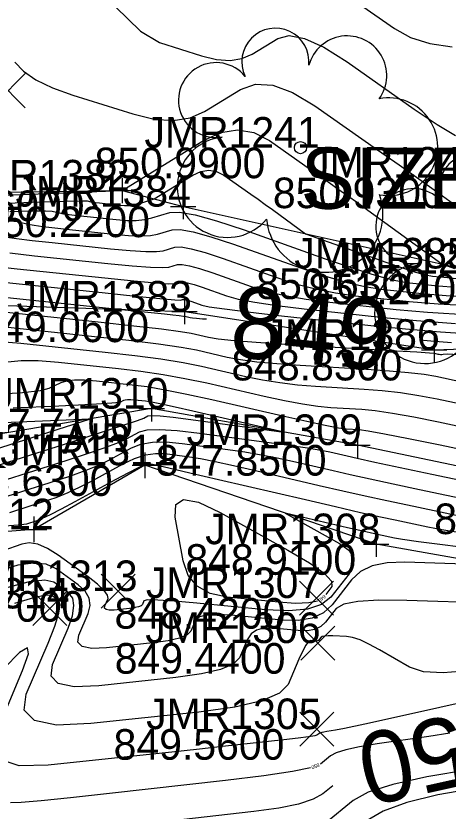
# Model space of a CAD drawing. Extents: x 1654928 to 1810050, y 486881 to 626330.
# Drawn here: x 1801514.13 to 1801531.06, y 489829.65 to 489860.85 of the extents above; entities that cross this region are included whole.
import ezdxf

# ---------------------------------------------------------------- set-up
doc = ezdxf.new("R2010")
doc.units = 0
for name, color, linetype in [('DR_X_Ditch', 7, 'Continuous'), ('DT_X_Contour_Major', 7, 'Continuous'), ('DT_X_Contour_Minor', 7, 'Continuous'), ('SV_X_Random_Point', 7, 'Continuous'), ('SV_X_Shot_Marker', 7, 'Continuous'), ('SV_X_Text_Comment', 7, 'Continuous'), ('SV_X_Text_Elevation', 7, 'Continuous'), ('SV_X_Text_Name', 7, 'Continuous'), ('SV_X_Toe_of_Slope', 7, 'Continuous'), ('SV_X_Top_of_Bank', 7, 'Continuous'), ('VG_X_Cells', 7, 'Continuous'), ('VG_X_Text', 7, 'Continuous')]:
    doc.layers.add(name, color=color, linetype=linetype)

msp = doc.modelspace()

# ---------------------------------------------------------------- linework, layer by layer
at = {"layer": 'DR_X_Ditch'}
msp.add_lwpolyline([(1801538.429, 489841.719), (1801527.515, 489844.014), (1801519.444, 489845.441), (1801503.521, 489842.761), (1801490.506, 489842.113), (1801478.561, 489839.498), (1801468.658, 489833.373), (1801465.597, 489830.762), (1801453.487, 489824.594)], dxfattribs=at)
at = {"layer": 'DT_X_Contour_Major'}
for points in [[(1801518.035, 489861.209), (1801519.01, 489860.254), (1801519.748, 489859.805), (1801521.403, 489859.283), (1801521.993, 489859.14), (1801522.52, 489859.104), (1801522.987, 489859.174), (1801523.391, 489859.351), (1801524.387, 489859.963), (1801524.837, 489860.077), (1801525.44, 489859.962), (1801526.197, 489859.615), (1801527.106, 489859.039), (1801529.736, 489857.194), (1801530.633, 489856.59), (1801531.351, 489856.161)], [(1801513.898, 489852.81), (1801514.172, 489852.781), (1801514.612, 489852.677), (1801514.837, 489852.634), (1801515.182, 489852.585), (1801515.647, 489852.528), (1801516.231, 489852.464), (1801517.95, 489852.283), (1801518.541, 489852.232), (1801519.025, 489852.215), (1801519.403, 489852.23), (1801519.674, 489852.28), (1801520.255, 489852.455), (1801520.568, 489852.469), (1801521.073, 489852.38), (1801521.77, 489852.186), (1801522.658, 489851.889), (1801525.281, 489850.958), (1801526.216, 489850.645), (1801527.055, 489850.402), (1801527.797, 489850.23), (1801528.443, 489850.129), (1801530.036, 489849.953), (1801530.982, 489849.881), (1801532.625, 489849.795)], [(1801512.039, 489849.987), (1801518.264, 489849.333), (1801519.952, 489849.156), (1801520.276, 489849.121), (1801520.524, 489849.092), (1801520.696, 489849.069), (1801520.793, 489849.052), (1801520.951, 489849.016), (1801521.044, 489849.002), (1801521.205, 489848.986), (1801521.435, 489848.969), (1801521.597, 489848.958)], [(1801529.956, 489848.137), (1801530.391, 489848.098), (1801531.202, 489848.038)], [(1801534.445, 489843.224), (1801530.748, 489844.002), (1801529.51, 489844.259), (1801528.571, 489844.445), (1801527.929, 489844.562), (1801527.585, 489844.609), (1801527.064, 489844.64), (1801526.763, 489844.68), (1801526.25, 489844.777), (1801525.525, 489844.931), (1801524.588, 489845.142), (1801521.807, 489845.78), (1801520.829, 489845.996), (1801519.981, 489846.166), (1801519.265, 489846.29), (1801518.678, 489846.368), (1801517.289, 489846.514), (1801516.811, 489846.552), (1801516.418, 489846.554), (1801516.112, 489846.521), (1801515.892, 489846.454), (1801515.42, 489846.226), (1801515.072, 489846.143), (1801514.382, 489846.065), (1801513.351, 489845.992)], [(1801512.593, 489842.29), (1801515.728, 489843.29), (1801516.781, 489843.631), (1801517.588, 489843.905), (1801518.149, 489844.111), (1801518.464, 489844.25), (1801518.977, 489844.53), (1801519.268, 489844.605), (1801519.757, 489844.621), (1801520.443, 489844.578), (1801521.327, 489844.476), (1801523.948, 489844.124), (1801524.84, 489844.002), (1801525.55, 489843.897), (1801526.078, 489843.81), (1801526.425, 489843.741), (1801527.107, 489843.583), (1801527.506, 489843.494), (1801528.193, 489843.345), (1801530.429, 489842.872), (1801534.177, 489842.084)], [(1801532.898, 489839.299), (1801529.368, 489839.415), (1801528.67, 489839.391), (1801528.09, 489839.268), (1801527.627, 489839.047), (1801527.281, 489838.728), (1801526.515, 489837.744), (1801526.177, 489837.43), (1801525.737, 489837.225), (1801525.194, 489837.129), (1801524.55, 489837.142), (1801522.696, 489837.322), (1801522.08, 489837.361), (1801521.619, 489837.344), (1801521.316, 489837.27), (1801521.169, 489837.139), (1801520.985, 489836.714), (1801520.84, 489836.565), (1801520.542, 489836.438), (1801520.092, 489836.333), (1801519.488, 489836.249), (1801517.676, 489836.055), (1801517.098, 489836.032), (1801516.724, 489836.107), (1801516.555, 489836.281), (1801516.59, 489836.553), (1801516.954, 489837.411), (1801517.033, 489837.722), (1801516.995, 489838.012), (1801516.842, 489838.281), (1801516.573, 489838.529), (1801515.701, 489839.162), (1801515.317, 489839.336), (1801514.819, 489839.38), (1801514.207, 489839.296), (1801513.482, 489839.083)], [(1801526.541, 489830.649), (1801526.157, 489830.333), (1801525.78, 489830.118), (1801525.204, 489829.93), (1801524.429, 489829.769), (1801523.455, 489829.635), (1801520.593, 489829.314), (1801519.572, 489829.211), (1801518.658, 489829.145), (1801517.85, 489829.115), (1801517.148, 489829.12), (1801515.416, 489829.184), (1801514.789, 489829.203), (1801514.203, 489829.213), (1801513.661, 489829.214)]]:
    msp.add_lwpolyline(points, dxfattribs=at)
at = {"layer": 'DT_X_Contour_Minor'}
for points in [[(1801527.426, 489861.424), (1801528.96, 489860.348), (1801529.595, 489859.999), (1801530.348, 489859.76), (1801531.219, 489859.631)], [(1801514.082, 489859.034), (1801514.42, 489858.676), (1801514.913, 489858.34), (1801515.56, 489858.028), (1801516.362, 489857.739), (1801518.706, 489857), (1801519.542, 489856.798), (1801520.29, 489856.746), (1801520.95, 489856.846), (1801521.523, 489857.096), (1801522.934, 489857.963), (1801523.512, 489858.167), (1801524.189, 489858.127), (1801524.964, 489857.844), (1801525.838, 489857.318), (1801528.3, 489855.592), (1801529.142, 489855), (1801529.822, 489854.52), (1801530.341, 489854.152), (1801530.697, 489853.896), (1801531.712, 489853.159)], [(1801510.049, 489853.677), (1801518.285, 489853.998), (1801521.481, 489855.963), (1801522.155, 489856.278), (1801522.81, 489856.382), (1801523.445, 489856.275), (1801524.06, 489855.956), (1801525.672, 489854.825), (1801526.275, 489854.4), (1801526.874, 489853.974), (1801527.47, 489853.547), (1801528.062, 489853.119), (1801530.815, 489851.116), (1801531.31, 489850.941)], [(1801513.758, 489853.5), (1801515.098, 489853.55), (1801516.07, 489853.582), (1801516.676, 489853.596), (1801516.914, 489853.593), (1801517.061, 489853.558), (1801517.136, 489853.544), (1801517.251, 489853.527), (1801517.406, 489853.508), (1801518.174, 489853.427), (1801518.379, 489853.412), (1801518.566, 489853.414), (1801518.735, 489853.433), (1801518.886, 489853.467), (1801519.546, 489853.667), (1801521.06, 489854.597), (1801521.379, 489854.747), (1801521.689, 489854.796), (1801521.99, 489854.745), (1801522.281, 489854.594), (1801523.331, 489853.857), (1801523.615, 489853.655), (1801523.897, 489853.453), (1801524.177, 489853.25), (1801525.481, 489852.302), (1801528.659, 489851.174), (1801529.282, 489850.96), (1801529.789, 489850.8), (1801530.181, 489850.694), (1801530.457, 489850.643), (1801531.039, 489850.579), (1801531.384, 489850.552)], [(1801513.895, 489853.179), (1801514.737, 489853.201), (1801515.287, 489853.203), (1801515.543, 489853.187), (1801515.837, 489853.117), (1801515.987, 489853.089), (1801516.217, 489853.056), (1801516.526, 489853.018), (1801516.916, 489852.975), (1801518.062, 489852.855), (1801518.471, 489852.825), (1801518.838, 489852.827), (1801519.164, 489852.86), (1801519.449, 489852.924), (1801520.153, 489853.138), (1801520.534, 489853.154), (1801521.146, 489853.046), (1801521.991, 489852.811), (1801523.067, 489852.451), (1801526.248, 489851.322), (1801527.343, 489850.946), (1801528.242, 489850.665), (1801528.944, 489850.478), (1801529.45, 489850.386), (1801530.537, 489850.266), (1801531.183, 489850.216)], [(1801513.688, 489852.18), (1801514.148, 489852.114), (1801514.767, 489852.038), (1801515.547, 489851.952), (1801517.838, 489851.712), (1801518.611, 489851.639), (1801519.213, 489851.602), (1801519.642, 489851.601), (1801519.899, 489851.635), (1801520.356, 489851.773), (1801520.603, 489851.784), (1801521.001, 489851.713), (1801521.549, 489851.561), (1801522.248, 489851.327), (1801524.313, 489850.595), (1801525.089, 489850.343), (1801525.868, 489850.139), (1801526.65, 489849.982), (1801527.436, 489849.872), (1801529.535, 489849.64), (1801530.679, 489849.548), (1801532.536, 489849.446)], [(1801513.888, 489851.548), (1801514.862, 489851.441), (1801517.726, 489851.14), (1801518.682, 489851.046), (1801519.4, 489850.99), (1801519.881, 489850.971), (1801520.124, 489850.99), (1801520.458, 489851.091), (1801520.638, 489851.099), (1801520.928, 489851.047), (1801521.328, 489850.936), (1801521.838, 489850.765), (1801523.345, 489850.231), (1801523.962, 489850.042), (1801524.681, 489849.876), (1801525.504, 489849.734), (1801526.429, 489849.615), (1801529.034, 489849.328), (1801530.25, 489849.221), (1801531.944, 489849.115)], [(1801513.008, 489851.057), (1801514.177, 489850.929), (1801517.614, 489850.568), (1801518.752, 489850.453), (1801519.587, 489850.377), (1801520.12, 489850.341), (1801520.35, 489850.345), (1801520.56, 489850.409), (1801520.673, 489850.414), (1801520.856, 489850.381), (1801521.108, 489850.311), (1801521.429, 489850.204), (1801522.377, 489849.867), (1801522.835, 489849.741), (1801523.494, 489849.613), (1801524.357, 489849.486), (1801525.422, 489849.358), (1801528.533, 489849.015), (1801529.821, 489848.893), (1801531.352, 489848.784)], [(1801513.493, 489850.418), (1801517.503, 489849.996), (1801518.822, 489849.859), (1801519.774, 489849.764), (1801520.358, 489849.711), (1801520.575, 489849.7), (1801520.661, 489849.726), (1801520.708, 489849.728), (1801520.783, 489849.715), (1801520.887, 489849.686), (1801521.019, 489849.642), (1801521.41, 489849.503), (1801521.707, 489849.439), (1801522.308, 489849.351), (1801523.21, 489849.238), (1801524.415, 489849.1), (1801528.032, 489848.702), (1801529.392, 489848.565), (1801530.76, 489848.453), (1801532.136, 489848.367)], [(1801508.55, 489849.771), (1801517.349, 489848.845), (1801518.753, 489848.693), (1801519.828, 489848.568), (1801520.576, 489848.47), (1801520.996, 489848.398), (1801521.678, 489848.241), (1801522.056, 489848.181), (1801522.68, 489848.116), (1801523.548, 489848.048), (1801524.661, 489847.976), (1801529.043, 489847.714), (1801529.834, 489847.664), (1801530.329, 489847.63), (1801530.527, 489847.611), (1801530.661, 489847.583), (1801530.712, 489847.575), (1801530.765, 489847.571), (1801530.82, 489847.571), (1801530.876, 489847.576), (1801531.029, 489847.594), (1801531.476, 489847.568)], [(1801512.83, 489848.736), (1801517.095, 489848.287), (1801518.551, 489848.127), (1801519.72, 489847.983), (1801520.602, 489847.855), (1801521.198, 489847.743), (1801522.406, 489847.466), (1801522.924, 489847.368), (1801523.572, 489847.281), (1801524.352, 489847.206), (1801525.262, 489847.142), (1801527.863, 489846.987), (1801528.765, 489846.926), (1801529.518, 489846.859), (1801530.124, 489846.787), (1801530.582, 489846.709), (1801531.607, 489846.494)], [(1801532.553, 489845.404), (1801530.638, 489845.807), (1801529.92, 489845.944), (1801529.202, 489846.055), (1801528.486, 489846.138), (1801527.77, 489846.194), (1801525.863, 489846.308), (1801525.156, 489846.364), (1801524.465, 489846.447), (1801523.791, 489846.556), (1801523.133, 489846.691), (1801521.401, 489847.089), (1801520.678, 489847.236), (1801519.807, 489847.378), (1801518.789, 489847.515), (1801517.623, 489847.648), (1801514.316, 489847.995), (1801513.179, 489848.084)], [(1801533.499, 489844.314), (1801530.693, 489844.904), (1801529.715, 489845.101), (1801528.887, 489845.25), (1801528.207, 489845.35), (1801527.677, 489845.401), (1801526.464, 489845.474), (1801525.959, 489845.522), (1801525.358, 489845.612), (1801524.658, 489845.743), (1801523.861, 489845.917), (1801521.604, 489846.434), (1801520.753, 489846.616), (1801519.894, 489846.772), (1801519.027, 489846.903), (1801518.15, 489847.008), (1801515.802, 489847.255), (1801514.995, 489847.318), (1801514.332, 489847.322), (1801513.815, 489847.266)], [(1801511.944, 489842.749), (1801515.988, 489844.039), (1801517.322, 489844.466), (1801518.292, 489844.78), (1801518.898, 489844.982), (1801519.14, 489845.071), (1801519.299, 489845.158), (1801519.449, 489845.173), (1801519.779, 489845.154), (1801520.291, 489845.101), (1801520.982, 489845.013), (1801524.632, 489844.523), (1801521.06, 489845.343), (1801520.37, 489845.499), (1801519.831, 489845.615), (1801519.443, 489845.692), (1801519.206, 489845.729), (1801518.775, 489845.774), (1801518.626, 489845.785), (1801518.505, 489845.786), (1801518.41, 489845.776), (1801518.341, 489845.755), (1801518.195, 489845.684), (1801517.893, 489845.65), (1801517.095, 489845.601), (1801515.804, 489845.536), (1801514.017, 489845.457)], [(1801510.41, 489842.926), (1801517.011, 489845.031), (1801508.098, 489844.648)], [(1801513.243, 489841.831), (1801515.469, 489842.541), (1801516.24, 489842.796), (1801516.884, 489843.029), (1801517.4, 489843.24), (1801517.789, 489843.428), (1801518.656, 489843.901), (1801519.024, 489844.045), (1801519.478, 489844.123), (1801520.02, 489844.133), (1801520.647, 489844.076), (1801522.436, 489843.836), (1801523.097, 489843.74), (1801523.74, 489843.632), (1801524.365, 489843.511), (1801524.971, 489843.378), (1801526.562, 489843.008), (1801527.221, 489842.857), (1801528.005, 489842.684), (1801528.914, 489842.487), (1801529.948, 489842.268), (1801532.873, 489841.653)], [(1801513.892, 489841.372), (1801515.21, 489841.792), (1801515.699, 489841.961), (1801516.18, 489842.153), (1801516.651, 489842.368), (1801517.113, 489842.607), (1801518.334, 489843.273), (1801518.779, 489843.486), (1801519.2, 489843.624), (1801519.596, 489843.687), (1801519.967, 489843.676), (1801520.924, 489843.548), (1801521.355, 489843.479), (1801521.931, 489843.367), (1801522.651, 489843.212), (1801523.517, 489843.015), (1801526.017, 489842.432), (1801526.936, 489842.221), (1801527.817, 489842.022), (1801528.661, 489841.837), (1801529.468, 489841.664), (1801531.568, 489841.223)], [(1801531.53, 489840.572), (1801530.82, 489840.687), (1801530.264, 489840.792), (1801528.987, 489841.06), (1801528.408, 489841.186), (1801527.63, 489841.36), (1801526.651, 489841.584), (1801525.472, 489841.857), (1801522.062, 489842.652), (1801520.938, 489842.913), (1801520.121, 489843.102), (1801519.612, 489843.217), (1801519.412, 489843.26), (1801519.287, 489843.277), (1801519.172, 489843.242), (1801518.921, 489843.125), (1801518.535, 489842.926), (1801518.012, 489842.645), (1801516.438, 489841.785), (1801515.902, 489841.497), (1801515.476, 489841.278), (1801515.158, 489841.126), (1801514.95, 489841.043), (1801514.541, 489840.913), (1801514.21, 489840.864), (1801513.521, 489840.815)], [(1801520.374, 489841.187), (1801520.398, 489841.681), (1801520.699, 489841.875), (1801521.277, 489841.771), (1801522.132, 489841.367), (1801524.78, 489839.893), (1801525.633, 489839.389), (1801526.206, 489838.982), (1801526.499, 489838.673), (1801526.512, 489838.461), (1801526.266, 489838.145)], [(1801532.074, 489839.943), (1801530.839, 489840.099), (1801529.908, 489840.221), (1801529.282, 489840.308), (1801528.96, 489840.361), (1801528.293, 489840.503), (1801527.6, 489840.66), (1801527.122, 489840.771), (1801524.684, 489841.339), (1801526.808, 489840.156), (1801527.173, 489839.892), (1801527.357, 489839.604), (1801527.36, 489839.294), (1801527.182, 489838.961), (1801526.466, 489838.042), (1801526.105, 489837.753), (1801525.558, 489837.574), (1801524.826, 489837.507), (1801523.907, 489837.55), (1801521.211, 489837.812), (1801520.323, 489837.891), (1801519.683, 489837.933), (1801519.289, 489837.936), (1801519.143, 489837.902), (1801519.082, 489837.76), (1801519.033, 489837.711), (1801518.934, 489837.669), (1801518.784, 489837.634), (1801518.583, 489837.606), (1801517.979, 489837.541), (1801517.786, 489837.533), (1801517.662, 489837.558), (1801517.605, 489837.616), (1801517.617, 489837.707), (1801517.738, 489837.993), (1801517.723, 489838.127), (1801517.587, 489838.313), (1801517.331, 489838.552), (1801516.953, 489838.843), (1801515.785, 489839.691), (1801515.367, 489839.957), (1801514.989, 489840.119), (1801514.652, 489840.176), (1801514.354, 489840.13), (1801513.614, 489839.868)], [(1801525.945, 489837.887), (1801525.607, 489837.818), (1801525.089, 489837.802), (1801524.416, 489837.846), (1801522.412, 489838.04), (1801521.74, 489838.185), (1801521.227, 489838.471), (1801520.874, 489838.901), (1801520.679, 489839.472), (1801520.374, 489841.187)], [(1801532.7, 489837.813), (1801529.44, 489837.921), (1801528.351, 489837.931), (1801527.529, 489837.881), (1801526.972, 489837.77), (1801526.682, 489837.599), (1801526.265, 489837.063), (1801526.08, 489836.891), (1801525.84, 489836.779), (1801525.544, 489836.727), (1801525.193, 489836.734), (1801524.182, 489836.832), (1801523.836, 489836.831), (1801523.556, 489836.755), (1801523.342, 489836.603), (1801523.194, 489836.375), (1801522.889, 489835.667), (1801522.647, 489835.419), (1801522.15, 489835.208), (1801521.399, 489835.033), (1801520.394, 489834.893), (1801517.373, 489834.57), (1801516.41, 489834.531), (1801515.787, 489834.656), (1801515.505, 489834.946), (1801515.563, 489835.4), (1801516.17, 489836.829), (1801516.342, 489837.318), (1801516.403, 489837.712), (1801516.353, 489838.011), (1801516.193, 489838.215), (1801515.616, 489838.634), (1801515.266, 489838.714), (1801514.648, 489838.641), (1801513.763, 489838.415)], [(1801531.855, 489835.16), (1801530.865, 489835.071), (1801530.095, 489835.12), (1801529.545, 489835.305), (1801528.373, 489835.984), (1801527.963, 489836.207), (1801527.612, 489836.369), (1801527.32, 489836.468), (1801527.087, 489836.506), (1801526.543, 489836.524), (1801526.362, 489836.526), (1801526.225, 489836.517), (1801526.132, 489836.499), (1801526.084, 489836.47), (1801526.014, 489836.381), (1801525.983, 489836.352), (1801525.943, 489836.334), (1801525.894, 489836.325), (1801525.836, 489836.326), (1801525.667, 489836.343), (1801525.592, 489836.302), (1801525.492, 489836.166), (1801525.368, 489835.936), (1801525.22, 489835.611), (1801524.792, 489834.62), (1801524.453, 489834.274), (1801523.758, 489833.977), (1801522.707, 489833.732), (1801521.299, 489833.537), (1801517.07, 489833.084), (1801515.722, 489833.029), (1801514.85, 489833.205), (1801514.455, 489833.61), (1801514.536, 489834.246), (1801515.386, 489836.247), (1801515.651, 489836.914), (1801515.811, 489837.412), (1801515.865, 489837.741), (1801515.813, 489837.902), (1801515.532, 489838.105), (1801515.3, 489838.123), (1801514.814, 489838.022), (1801514.075, 489837.803)], [(1801513.418, 489832.88), (1801514.391, 489835.17), (1801514.62, 489835.821), (1801514.579, 489836.055), (1801514.266, 489835.872), (1801513.682, 489835.272)], [(1801535.845, 489834.855), (1801530.737, 489833.714), (1801529.045, 489833.338), (1801527.8, 489833.063), (1801527.002, 489832.891), (1801526.652, 489832.822), (1801526.313, 489832.772), (1801526.199, 489832.754), (1801526.11, 489832.734), (1801526.047, 489832.714), (1801526.009, 489832.694), (1801525.942, 489832.639), (1801525.841, 489832.611), (1801525.588, 489832.572), (1801525.184, 489832.52), (1801524.628, 489832.455), (1801522.223, 489832.186), (1801521.323, 489832.088), (1801520.243, 489831.971), (1801518.984, 489831.836), (1801515.387, 489831.451), (1801514.252, 489831.432), (1801513.546, 489831.663)], [(1801531.129, 489832.716), (1801530.308, 489832.584), (1801528.278, 489832.289), (1801527.593, 489832.176), (1801527.06, 489832.06), (1801526.68, 489831.941), (1801526.453, 489831.818), (1801526.058, 489831.492)], [(1801548.136, 489829.56), (1801547.136, 489829.805), (1801546.149, 489830.07), (1801545.175, 489830.354), (1801542.596, 489831.137), (1801541.737, 489831.393), (1801541.094, 489831.574), (1801540.667, 489831.681), (1801540.456, 489831.712), (1801540.182, 489831.696), (1801539.883, 489831.66), (1801539.192, 489831.565), (1801538.11, 489831.41), (1801536.636, 489831.197), (1801532.182, 489830.548), (1801530.662, 489830.287), (1801529.441, 489829.989), (1801528.52, 489829.655), (1801527.898, 489829.284)], [(1801525.666, 489831.345), (1801524.97, 489831.203), (1801523.848, 489831.037), (1801522.337, 489830.854), (1801517.79, 489830.344), (1801516.27, 489830.177), (1801515.118, 489830.061), (1801514.335, 489829.994), (1801513.92, 489829.978)], [(1801531.947, 489831.284), (1801530.234, 489831), (1801528.895, 489830.702), (1801527.93, 489830.391), (1801527.34, 489830.066), (1801526.264, 489829.18)]]:
    msp.add_lwpolyline(points, dxfattribs=at)
at = {"layer": 'SV_X_Random_Point'}
for p, q in [((1801513.157, 489857.246), (1801514.49, 489858.581)), ((1801513.157, 489858.581), (1801514.49, 489857.246)), ((1801517.463, 489837.616), (1801518.797, 489838.951)), ((1801517.463, 489838.951), (1801518.797, 489837.616)), ((1801525.243, 489837.344), (1801526.576, 489838.679)), ((1801525.243, 489838.679), (1801526.576, 489837.344)), ((1801514.785, 489836.936), (1801516.118, 489838.271)), ((1801514.785, 489838.271), (1801516.118, 489836.936)), ((1801525.297, 489835.577), (1801526.631, 489836.912)), ((1801525.297, 489836.912), (1801526.631, 489835.577)), ((1801525.254, 489832.202), (1801526.587, 489833.537)), ((1801525.254, 489833.537), (1801526.587, 489832.202))]:
    msp.add_line(p, q, dxfattribs=at)
at = {"layer": 'SV_X_Shot_Marker'}
for p, q in [((1801518.285, 489854.498), (1801518.285, 489853.498)), ((1801517.785, 489853.998), (1801518.785, 489853.998)), ((1801518.285, 489853.998), (1801518.285, 489853.998)), ((1801520.681, 489853.868), (1801520.681, 489852.868)), ((1801520.181, 489853.368), (1801521.181, 489853.368)), ((1801520.681, 489853.368), (1801520.681, 489853.368)), ((1801520.732, 489849.749), (1801520.732, 489848.749)), ((1801520.232, 489849.249), (1801521.232, 489849.249)), ((1801520.732, 489849.249), (1801520.732, 489849.249)), ((1801530.519, 489848.247), (1801530.519, 489847.247)), ((1801530.019, 489847.747), (1801531.019, 489847.747)), ((1801530.519, 489847.747), (1801530.519, 489847.747)), ((1801519.444, 489845.941), (1801519.444, 489844.941)), ((1801518.944, 489845.441), (1801519.944, 489845.441)), ((1801519.444, 489845.441), (1801519.444, 489845.441)), ((1801527.515, 489844.514), (1801527.515, 489843.514)), ((1801527.015, 489844.014), (1801528.015, 489844.014)), ((1801527.515, 489844.014), (1801527.515, 489844.014)), ((1801519.185, 489843.717), (1801519.185, 489842.717)), ((1801518.685, 489843.217), (1801519.685, 489843.217)), ((1801519.185, 489843.217), (1801519.185, 489843.217)), ((1801514.834, 489841.206), (1801514.834, 489840.206)), ((1801514.334, 489840.706), (1801515.334, 489840.706)), ((1801514.834, 489840.706), (1801514.834, 489840.706)), ((1801528.242, 489840.624), (1801528.242, 489839.624)), ((1801527.742, 489840.124), (1801528.742, 489840.124)), ((1801528.242, 489840.124), (1801528.242, 489840.124))]:
    msp.add_line(p, q, dxfattribs=at)
at = {"layer": 'SV_X_Toe_of_Slope'}
for points in [[(1801453.22, 489833.952), (1801462.62, 489833.764), (1801469.81, 489840.55), (1801480.323, 489844.16), (1801485.248, 489845.996), (1801491.16, 489848.502), (1801498.28, 489846.461), (1801505.556, 489847.392), (1801507.978, 489849.684), (1801520.732, 489849.249), (1801530.519, 489847.747), (1801557.678, 489848.692)], [(1801548.771, 489840.76), (1801538.587, 489838.29), (1801528.242, 489840.124), (1801519.185, 489843.217), (1801514.834, 489840.706), (1801503.746, 489839.863), (1801493.235, 489835.949), (1801481.982, 489831.828), (1801478.469, 489833.99), (1801472.566, 489830.006), (1801464.849, 489824.991), (1801462.27, 489825.427), (1801460.621, 489820.525)]]:
    msp.add_lwpolyline(points, dxfattribs=at)
at = {"layer": 'SV_X_Top_of_Bank'}
msp.add_lwpolyline([(1801452.193, 489836.758), (1801459.513, 489846.009), (1801465.887, 489850.179), (1801473.853, 489849.345), (1801479.986, 489850.885), (1801482.71, 489854.488), (1801486.035, 489852.905), (1801488.583, 489850.107), (1801492.084, 489852.448), (1801498.522, 489852.672), (1801506.396, 489853.841), (1801518.285, 489853.998), (1801520.681, 489853.368), (1801531.615, 489850.939), (1801557.484, 489854.39)], dxfattribs=at)
at = {"layer": 'VG_X_Cells'}
msp.add_circle((1801525.28, 489855.679), 0.24, dxfattribs=at)
for centre, radius, start, end in [((1801524.296, 489859.047), 1.317, 354.0047, 205.9741), ((1801527.106, 489858.509), 1.553, 323.83, 165.0376), ((1801521.97, 489857.544), 1.471, 39.0625, 279.5412), ((1801528.74, 489855.715), 1.915, 259.1453, 101.4596), ((1801522.426, 489854.131), 1.974, 96.1722, 320.5737), ((1801532.027, 489854.102), 1.317, 354.0047, 205.9741), ((1801529.702, 489852.599), 1.471, 39.0625, 279.5412), ((1801526.226, 489853.074), 2.284, 184.9476, 19.4572), ((1801530.158, 489849.186), 1.974, 96.1722, 320.5737)]:
    msp.add_arc(centre, radius, start, end, dxfattribs=at)

# ---------------------------------------------------------------- texts
at = {"layer": 'DT_X_Contour_Major'}
for s, rotation, p in [('849', 354.3905, (1801522.45, 489847.502)), ('850', 192.5187, (1801533.427, 489833.927))]:
    msp.add_text(s, height=2.8, rotation=rotation, dxfattribs=at).set_placement(p)
at = {"layer": 'DT_X_Contour_Minor'}
for s, rotation, p in [('849', 218.7614, (1801526.206, 489838.149)), ('850', 200.6348, (1801525.994, 489831.538))]:
    msp.add_text(s, height=0.14, rotation=rotation, dxfattribs=at).set_placement(p)
at = {"layer": 'SV_X_Text_Comment'}
msp.add_text('EL*CMP FD0 SIZE? 0.50 LOCATION? TOP OF PIPE CONDITION? FAIR', height=1.2, dxfattribs=at).set_placement((1801466.022, 489843.668))
at = {"layer": 'SV_X_Text_Elevation'}
for s, p in [('850.9900', (1801517.211, 489854.479)), ('850.9300', (1801524.198, 489853.305)), ('850.6000', (1801510.122, 489852.798)), ('850.2200', (1801512.687, 489852.168)), ('850.6300', (1801523.546, 489849.739)), ('851.2400', (1801525.576, 489849.535)), ('849.0600', (1801512.654, 489848.049)), ('848.8300', (1801522.573, 489846.547)), ('847.7100', (1801512.027, 489844.241)), ('847.8500', (1801519.607, 489842.814)), ('848.6300', (1801511.22, 489842.017)), ('847.8500', (1801530.521, 489840.519)), ('848.9100', (1801520.769, 489838.924)), ('848.7000', (1801510.109, 489837.084)), ('848.4200', (1801517.992, 489836.811)), ('849.4400', (1801517.999, 489835.045)), ('849.5600', (1801517.956, 489831.669))]:
    msp.add_text(s, height=1.2, dxfattribs=at).set_placement(p)
at = {"layer": 'SV_X_Text_Name'}
for s, p in [('JMR1241', (1801519.166, 489855.679)), ('JMR1240', (1801525.616, 489854.505)), ('JMR1382', (1801511.719, 489853.998)), ('JMR1384', (1801514.115, 489853.368)), ('JMR1385', (1801525.039, 489850.939)), ('JMR1242', (1801526.474, 489850.735)), ('JMR1383', (1801514.157, 489849.249)), ('JMR1386', (1801523.868, 489847.747)), ('JMR1310', (1801513.237, 489845.441)), ('JMR1309', (1801520.817, 489844.014)), ('JMR1311', (1801513.516, 489843.217)), ('JMR1312', (1801508.741, 489840.706)), ('JMR1308', (1801521.544, 489840.124)), ('JMR1313', (1801512.028, 489838.284)), ('JMR1307', (1801519.221, 489838.011)), ('JMR1314', (1801509.358, 489837.603)), ('JMR1306', (1801519.2, 489836.245)), ('JMR1305', (1801519.232, 489832.869))]:
    msp.add_text(s, height=1.2, dxfattribs=at).set_placement(p)
at = {"layer": 'VG_X_Text'}
msp.add_text('SIZE? 18" KIND? MAPLE', height=2.4, dxfattribs=at).set_placement((1801525.28, 489853.28))

doc.saveas('drawing.dxf')
